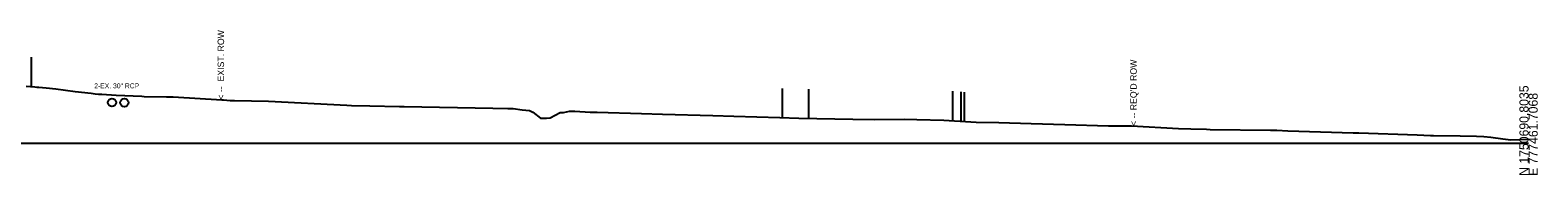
# Model space of a CAD drawing. Extents: x 776426 to 854588, y 1736205 to 1756790.
# Drawn here: x 805212.5 to 805673.6, y 1753705.1 to 1753749.4 of the extents above; entities that cross this region are included whole.
import ezdxf

# ---------------------------------------------------------------- set-up
doc = ezdxf.new("R2010")
doc.units = 0
for name, color, linetype in [('63', 7, 'Continuous'), ('DTM CONTOURS_MAJOR_TX', 7, 'Continuous'), ('DTM_X_FLOW_ARROWS', 7, 'Continuous'), ('TRANS_CURB_GUTTER', 7, 'Continuous'), ('TRANS_EOP_PAVED', 7, 'Continuous'), ('TRANS_UNPAVED_SHOULDERS', 7, 'Continuous'), ('XS_P_ROW', 7, 'Continuous'), ('XS_X_DRAINAGE', 7, 'Continuous'), ('XS_X_ROW', 7, 'Continuous'), ('XS_X_TX', 7, 'Continuous')]:
    doc.layers.add(name, color=color, linetype=linetype)

msp = doc.modelspace()

# ---------------------------------------------------------------- linework, layer by layer
at = {"layer": '63'}
msp.add_line((805212.79, 1753741.1), (805212.79, 1753732.1), dxfattribs=at)
msp.add_line((805212.79, 1753741.1), (805212.79, 1753732.1), dxfattribs=at)
at = {"layer": 'DTM CONTOURS_MAJOR_TX'}
msp.add_line((805170.79, 1753714.76), (805670.79, 1753714.76), dxfattribs=at)
at = {"layer": 'DTM_X_FLOW_ARROWS'}
msp.add_lwpolyline([(805211.24, 1753732.25), (805213.9, 1753731.98), (805214.51, 1753731.92), (805215.12, 1753731.88), (805217.36, 1753731.68), (805220.34, 1753731.44), (805226.2, 1753730.6), (805231.08, 1753730.09), (805232.35, 1753729.89), (805233.38, 1753729.79), (805234.41, 1753729.75), (805238.76, 1753729.43), (805246.63, 1753729.15), (805247.29, 1753729.09), (805254.18, 1753728.98), (805254.88, 1753728.97), (805256.23, 1753728.92), (805271.08, 1753728.06), (805271.64, 1753728.03), (805273.68, 1753727.89), (805274.94, 1753727.86), (805285.34, 1753727.62), (805309.34, 1753726.38), (805310.71, 1753726.33), (805316.37, 1753726.16), (805325.46, 1753726), (805326.82, 1753725.98), (805353.96, 1753725.52), (805358.6, 1753725.41), (805360.18, 1753725.37), (805362.98, 1753725), (805365.2, 1753724.81), (805366.18, 1753724.23), (805368.54, 1753722.42), (805370.38, 1753722.42), (805371.5, 1753722.53), (805374.55, 1753724.13), (805375.62, 1753724.14), (805377.4, 1753724.62), (805379.09, 1753724.53), (805383.75, 1753724.26), (805385.89, 1753724.31), (805399.46, 1753723.88), (805405.89, 1753723.66), (805421.26, 1753723.29), (805427.7, 1753723.09), (805441.73, 1753722.59), (805447.54, 1753722.41), (805464.07, 1753722.15), (805470.84, 1753722.04), (805479.92, 1753722.16), (805483.69, 1753722.02), (805491.9, 1753721.87), (805501.83, 1753721.19), (805508.77, 1753721.06), (805518.6, 1753720.77), (805528.91, 1753720.46), (805542.34, 1753720.13), (805549.33, 1753720.05), (805563.71, 1753719.31), (805567.47, 1753719.2), (805572.33, 1753719.04), (805573.42, 1753719), (805591.81, 1753718.77), (805593.83, 1753718.71), (805597.13, 1753718.56), (805617.15, 1753717.97), (805618.91, 1753717.95), (805636.69, 1753717.31), (805640.76, 1753717.17), (805641.73, 1753717.16), (805649.91, 1753717.06), (805654.83, 1753716.88), (805657.06, 1753716.79), (805659.27, 1753716.6), (805662.91, 1753716.09), (805665.33, 1753715.78), (805668.15, 1753715.89), (805670.79, 1753715.99)], dxfattribs=at)
at = {"layer": 'TRANS_CURB_GUTTER'}
for p, q in [((805497.17, 1753730.51), (805497.17, 1753721.51)), ((805497.17, 1753730.51), (805497.17, 1753721.51)), ((805498.15, 1753730.44), (805498.15, 1753721.44)), ((805498.15, 1753730.44), (805498.15, 1753721.44))]:
    msp.add_line(p, q, dxfattribs=at)
at = {"layer": 'TRANS_EOP_PAVED'}
for p, q in [((805450.55, 1753731.36), (805450.55, 1753722.36)), ((805450.55, 1753731.36), (805450.55, 1753722.36)), ((805494.59, 1753730.68), (805494.59, 1753721.68)), ((805494.59, 1753730.68), (805494.59, 1753721.68))]:
    msp.add_line(p, q, dxfattribs=at)
at = {"layer": 'TRANS_UNPAVED_SHOULDERS'}
msp.add_line((805442.52, 1753731.56), (805442.52, 1753722.56), dxfattribs=at)
msp.add_line((805442.52, 1753731.56), (805442.52, 1753722.56), dxfattribs=at)
at = {"layer": 'XS_X_DRAINAGE'}
for centre in [(805237.49, 1753727.24), (805241.29, 1753727.19)]:
    msp.add_circle(centre, 1.25, dxfattribs=at)

# ---------------------------------------------------------------- texts
at = {"layer": 'DTM CONTOURS_MAJOR_TX'}
for s, p in [('N 1750690.8035', (805670.79, 1753704.76)), ('E 777461.7068', (805673.59, 1753704.76))]:
    msp.add_text(s, height=2.8, rotation=90, dxfattribs=at).set_placement(p)
at = {"layer": 'XS_P_ROW'}
msp.add_text("< -- REQ'D ROW", height=2, rotation=90, dxfattribs=at).set_placement((805550.95, 1753720.02))
at = {"layer": 'XS_X_ROW'}
msp.add_text('< --  EXIST. ROW', height=2, rotation=90, dxfattribs=at).set_placement((805271.79, 1753728.08))
at = {"layer": 'XS_X_TX'}
msp.add_text('2-EX. 30" RCP', height=1.5, dxfattribs=at).set_placement((805232.06, 1753731.58))

doc.saveas('drawing.dxf')
